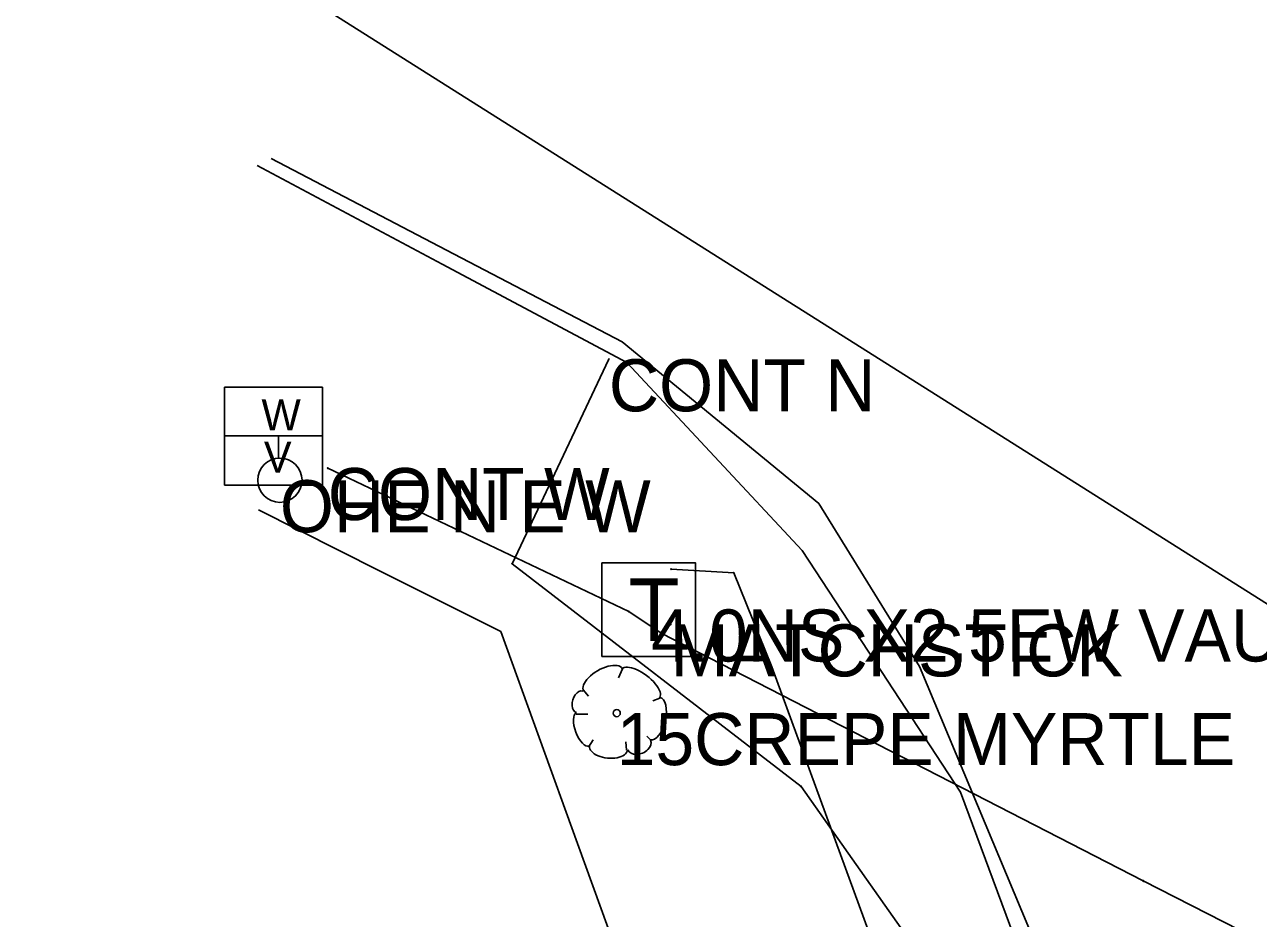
# Model space of a CAD drawing. Extents: x 997398 to 1003416, y 334596 to 337085.
# Drawn here: x 999476.7 to 999595.3, y 336572.9 to 336658.7 of the extents above; entities that cross this region are included whole.
import ezdxf

# ---------------------------------------------------------------- set-up
doc = ezdxf.new("R2010")
doc.units = 0
for name, color, linetype in [('Default', 7, 'Continuous'), ('S_CURB', 7, 'Continuous'), ('S_EDGE_PAVEMENT', 7, 'Continuous'), ('S_FIBER_OPTIC_CABLE', 7, 'Continuous'), ('S_FIBER_OPTIC_CABLE_ANNOT', 7, 'Continuous'), ('S_GAS_UTILITIES', 7, 'Continuous'), ('S_GAS_UTILITIES_ANNOT', 7, 'Continuous'), ('S_SHOULDER', 7, 'Continuous'), ('S_TELEPHONE_UTILITIES', 7, 'Continuous'), ('S_TELEPHONE_UTILITIES_ANNOT', 7, 'Continuous'), ('S_TREE', 7, 'Continuous'), ('S_TREE_ANNOT', 7, 'Continuous'), ('S_UTILITY_POLE', 7, 'Continuous'), ('S_UTILITY_POLE_ANNOT', 7, 'Continuous'), ('S_UTL_PT_SYM', 7, 'Continuous'), ('S_WATER_UTILITIES', 7, 'Continuous')]:
    doc.layers.add(name, color=color, linetype=linetype)

msp = doc.modelspace()

# ---------------------------------------------------------------- linework, layer by layer
at = {"layer": 'Default'}
msp.add_line((999737.12, 336514.03), (999233.93, 336831.87), dxfattribs=at)
at = {"layer": 'S_CURB'}
msp.add_lwpolyline([(999499.2, 336612.11), (999510.84, 336606.26), (999522.49, 336600.42), (999529.87, 336580.07), (999537.25, 336559.73), (999541.6, 336547.79), (999545.95, 336535.85), (999550.29, 336523.9), (999554.64, 336511.96), (999561.97, 336489.39), (999569.3, 336466.82), (999574.03, 336451.55), (999576.61, 336447.06), (999581.43, 336446.09), (999583.61, 336447.7)], dxfattribs=at)
at = {"layer": 'S_EDGE_PAVEMENT'}
msp.add_lwpolyline([(999589.82, 336474.39), (999589.18, 336494.63), (999588.54, 336514.87), (999584.75, 336534.22), (999580.96, 336553.58), (999571.86, 336575.32), (999562.76, 336597.06), (999553.06, 336612.72), (999534.16, 336628.27), (999517.28, 336637.07), (999500.4, 336645.87)], dxfattribs=at)
at = {"layer": 'S_FIBER_OPTIC_CABLE'}
for p, q in [((999505.85, 336616.14), (999534.79, 336602.36)), ((999544.88, 336606.08), (999538.86, 336606.43)), ((999548.55, 336597.05), (999544.88, 336606.08)), ((999534.79, 336602.36), (999537.92, 336600.26)), ((999537.92, 336600.26), (999584.26, 336576.46)), ((999559.26, 336567.76), (999548.55, 336597.05)), ((999584.26, 336576.46), (999614.5, 336561.11))]:
    msp.add_line(p, q, dxfattribs=at)
at = {"layer": 'S_GAS_UTILITIES'}
for p, q in [((999523.59, 336606.94), (999532.88, 336626.59)), ((999551.37, 336585.53), (999523.59, 336606.94)), ((999561.55, 336571.09), (999551.37, 336585.53))]:
    msp.add_line(p, q, dxfattribs=at)
at = {"layer": 'S_SHOULDER'}
msp.add_lwpolyline([(999499.08, 336645.2), (999516.84, 336635.74), (999534.6, 336626.27), (999551.48, 336608.21), (999559.08, 336596.6), (999566.68, 336584.99), (999573.81, 336565.85), (999580.94, 336546.72), (999584.24, 336528.84), (999587.55, 336510.97), (999588.43, 336496.76), (999589.31, 336482.55)], dxfattribs=at)
at = {"layer": 'S_TELEPHONE_UTILITIES'}
msp.add_lwpolyline([(999532.21, 336598.03), (999532.21, 336607.03), (999541.21, 336607.03), (999541.21, 336598.03)], close=True, dxfattribs=at)
at = {"layer": 'S_TREE'}
for p, q in [((999534.2, 336596.83), (999533.81, 336595.98)), ((999530.4, 336594.82), (999530.91, 336594.23)), ((999537.77, 336594.04), (999537.11, 336593.77)), ((999529.74, 336592.49), (999530.87, 336592.49)), ((999530.91, 336589.31), (999531.37, 336590.01)), ((999536.99, 336589.93), (999536.53, 336590.36)), ((999534.59, 336589.04), (999534.51, 336589.82))]:
    msp.add_line(p, q, dxfattribs=at)
msp.add_circle((999533.64, 336592.59), 0.341, dxfattribs=at)
for centre, major_axis, ratio, start_param, end_param in [((999532.31, 336595.79), (1.86, 1.08), 0.471018, 0, 3.141593), ((999535.96, 336595.46), (-1.81, 1.36), 0.405113, 3.141593, 6.283186), ((999530.07, 336593.67), (0.31, 1.03), 0.646762, 0, 3.141593), ((999537.32, 336592.06), (0.46, 2.04), 0.482994, 3.141593, 6.283185), ((999530.38, 336591.02), (-0.61, 1.6), 0.420543, 6.283185, 9.424777), ((999535.8, 336589.53), (1.09, 0.46), 0.711534, 3.141592, 6.283185), ((999532.84, 336589.24), (-1.83, 0.19), 0.529943, 0, 3.141593)]:
    msp.add_ellipse(centre, major_axis=major_axis, ratio=ratio, start_param=start_param, end_param=end_param, dxfattribs=at)
at = {"layer": 'S_UTILITY_POLE'}
msp.add_line((999501.13, 336617.11), (999501.13, 336619.22), dxfattribs=at)
msp.add_circle((999501.25, 336614.97), 2.13, dxfattribs=at)
at = {"layer": 'S_UTL_PT_SYM'}
for points in [[(999532.88, 336626.59), (999532.88, 336626.64), (999532.88, 336626.59), (999532.83, 336626.59), (999532.88, 336626.59), (999532.88, 336626.54), (999532.88, 336626.59), (999532.93, 336626.59)], [(999505.85, 336616.14), (999505.85, 336616.19), (999505.85, 336616.14), (999505.8, 336616.14), (999505.85, 336616.14), (999505.85, 336616.09), (999505.85, 336616.14), (999505.9, 336616.14)], [(999523.59, 336606.94), (999523.59, 336606.99), (999523.59, 336606.94), (999523.54, 336606.94), (999523.59, 336606.94), (999523.59, 336606.89), (999523.59, 336606.94), (999523.64, 336606.94)], [(999538.86, 336606.43), (999538.86, 336606.48), (999538.86, 336606.43), (999538.81, 336606.43), (999538.86, 336606.43), (999538.86, 336606.38), (999538.86, 336606.43), (999538.91, 336606.43)], [(999544.88, 336606.08), (999544.88, 336606.13), (999544.88, 336606.08), (999544.83, 336606.08), (999544.88, 336606.08), (999544.88, 336606.03), (999544.88, 336606.08), (999544.93, 336606.08)], [(999534.79, 336602.36), (999534.79, 336602.41), (999534.79, 336602.36), (999534.74, 336602.36), (999534.79, 336602.36), (999534.79, 336602.31), (999534.79, 336602.36), (999534.84, 336602.36)], [(999538.83, 336601.12), (999538.83, 336601.17), (999538.83, 336601.12), (999538.78, 336601.12), (999538.83, 336601.12), (999538.83, 336601.07), (999538.83, 336601.12), (999538.88, 336601.12)], [(999537.92, 336600.26), (999537.92, 336600.31), (999537.92, 336600.26), (999537.87, 336600.26), (999537.92, 336600.26), (999537.92, 336600.21), (999537.92, 336600.26), (999537.97, 336600.26)], [(999548.55, 336597.05), (999548.55, 336597.1), (999548.55, 336597.05), (999548.5, 336597.05), (999548.55, 336597.05), (999548.55, 336597), (999548.55, 336597.05), (999548.6, 336597.05)], [(999551.37, 336585.53), (999551.37, 336585.58), (999551.37, 336585.53), (999551.32, 336585.53), (999551.37, 336585.53), (999551.37, 336585.48), (999551.37, 336585.53), (999551.42, 336585.53)], [(999584.26, 336576.46), (999584.26, 336576.51), (999584.26, 336576.46), (999584.21, 336576.46), (999584.26, 336576.46), (999584.26, 336576.41), (999584.26, 336576.46), (999584.31, 336576.46)]]:
    msp.add_lwpolyline(points, dxfattribs=at)
at = {"layer": 'S_WATER_UTILITIES'}
for p, q in [((999495.93, 336623.91), (999505.34, 336623.91)), ((999495.93, 336614.49), (999495.93, 336623.91)), ((999505.34, 336623.91), (999505.34, 336614.49)), ((999495.93, 336619.22), (999505.34, 336619.22)), ((999505.34, 336614.49), (999495.93, 336614.49))]:
    msp.add_line(p, q, dxfattribs=at)

# ---------------------------------------------------------------- texts
at = {"layer": 'S_FIBER_OPTIC_CABLE_ANNOT'}
for s, p in [('CONT W', (999505.85, 336611.14)), ('MATCHSTICK', (999538.83, 336596.12))]:
    msp.add_text(s, height=5, dxfattribs=at).set_placement(p)
at = {"layer": 'S_GAS_UTILITIES_ANNOT'}
msp.add_text('CONT N', height=5, dxfattribs=at).set_placement((999532.88, 336621.59))
at = {"layer": 'S_TELEPHONE_UTILITIES'}
msp.add_text('T', height=6, rotation=360, dxfattribs=at).set_placement((999534.78, 336599.53))
at = {"layer": 'S_TELEPHONE_UTILITIES_ANNOT'}
msp.add_text('4.0NS X2.5EW VAULT.. ..WINDSTRE', height=5, dxfattribs=at).set_placement((999536.94, 336597.55))
at = {"layer": 'S_TREE_ANNOT'}
msp.add_text('15CREPE MYRTLE', height=5, dxfattribs=at).set_placement((999533.64, 336587.59))
at = {"layer": 'S_UTILITY_POLE_ANNOT'}
msp.add_text('OHE N E W', height=5, dxfattribs=at).set_placement((999501.25, 336609.97))
at = {"layer": 'S_WATER_UTILITIES'}
for s, p in [('W', (999499.48, 336619.75)), ('V', (999499.71, 336615.69))]:
    msp.add_text(s, height=3, rotation=360, dxfattribs=at).set_placement(p)

doc.saveas('drawing.dxf')
